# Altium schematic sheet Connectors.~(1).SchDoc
size A; SheetNumber: 1; SheetTotal: 1
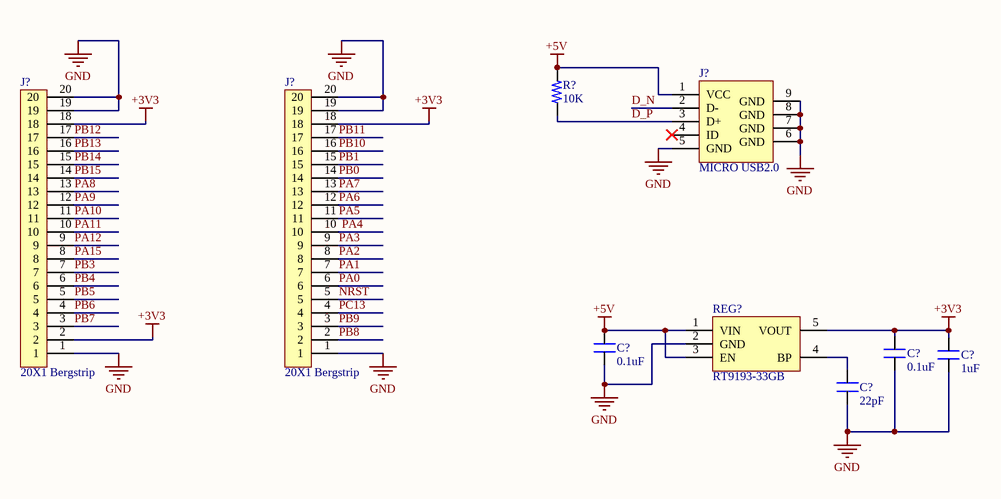
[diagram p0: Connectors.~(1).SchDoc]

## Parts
(Parts that share a designator on the sheet are numbered #1, #2 ... from top to bottom, then left to right.)
C?#1  0.1uF  [CAP_0805]
C?#2  0.1uF  [CAP_0805]
C?#3  1uF  [CAP_0805]
C?#4  22pF  [CAP_0805]
J?#1  MICRO USB2.0  [CON_10118192-0001LF_SMD]
J?#2  20X1 Bergstrip  [CON20_100_40D72_TH_ST]
J?#3  20X1 Bergstrip  [CON20_100_40D72_TH_ST]
R?  10K  [RES_0805]
REG?  RT9193-33GB  [SOT23-5]

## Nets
+3V3: C?#2.2 C?#3.2 J?#2.2 J?#2.18 J?#3.18 REG?.5(VOUT)
+5V: C?#1.2 J?#1.1(VCC) R?.2 REG?.1(VIN) REG?.3(EN)
GND: C?#1.1 C?#2.1 C?#3.1 C?#4.1 J?#1.5(GND) J?#1.6(GND) J?#1.7(GND) J?#1.8(GND) J?#1.9(GND) J?#2.1 J?#2.19 J?#2.20 J?#3.1 J?#3.19 J?#3.20 REG?.2(GND)
D_N: J?#1.2(D-)
D_P: J?#1.3(D+) R?.1
NRST: J?#3.5
PA0: J?#3.6
PA1: J?#3.7
PA2: J?#3.8
PA3: J?#3.9
PA4: J?#3.10
PA5: J?#3.11
PA6: J?#3.12
PA7: J?#3.13
PA8: J?#2.13
PA9: J?#2.12
PA10: J?#2.11
PA11: J?#2.10
PA12: J?#2.9
PA15: J?#2.8
PB0: J?#3.14
PB1: J?#3.15
PB3: J?#2.7
PB4: J?#2.6
PB5: J?#2.5
PB6: J?#2.4
PB7: J?#2.3
PB8: J?#3.2
PB9: J?#3.3
PB10: J?#3.16
PB11: J?#3.17
PB12: J?#2.17
PB13: J?#2.16
PB14: J?#2.15
PB15: J?#2.14
PC13: J?#3.4
NetC?#4_2: C?#4.2 REG?.4(BP)

Not connected (* = marked no-connect by the designer): J?#1 4(ID)*

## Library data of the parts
C?#1 C?#2 = CAP_0.1uF-50V-5%-0805: 0.1µF ±5% 50V Ceramic Capacitor X7R 0805 (2012 Metric); Manufacturer: KEMET; Manufacturing Part Number: C0805C104J5RACTU
C?#3 = CAP_1uF-50V-5%-0805: 1µF ±5% 50V Ceramic Capacitor X7R 0805 (2012 Metric); Manufacturer: Yageo; Manufacturing Part Number: CC0805JKX7R9BB105
C?#4 = CAP_22pF-50V-5%-0805: 22pF ±5% 50V Ceramic Capacitor C0G, NP0 0805 (2012 Metric); Manufacturer: KEMET; Manufacturer Part Number: C0805C220J5GACTU
J?#1 = CON-USB_10118192-0002LF-SMD: USB - micro B USB 2.0 Receptacle Connector 5 Position Surface Mount, Right Angle; Manufacturer: Amphenol ICC (FCI)
J?#2 J?#3 = CON-BS-PLG_20X1-100-TH-ST: 20 pin, 1 row, 2.54mm pitch bergstrip; Manufacturer: NA
R? = RES_10K-0.125W-1%-0805: 10 kOhms ±1% 0.125W, 1/8W Chip Resistor 0805 (2012 Metric) Moisture Resistant Thick Film; Manufacturer: Yageo; Manufacturing Part Number: RC0805FR-0710KL
REG? = REG_3.3V-5.5V-0.3A-SOT-23-5: Linear Voltage Regulator IC 1 Output 300mA SOT-23-5; Manufacturer: Richtek USA Inc.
